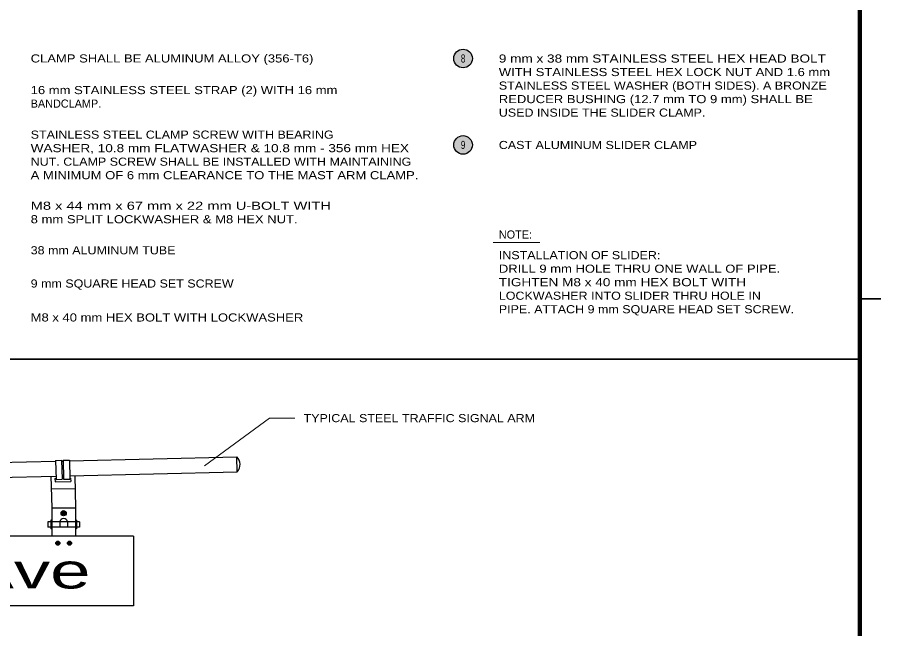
# Model space of a CAD drawing. Extents: x 312583 to 312853, y 144376 to 144586.
# Drawn here: x 312771.1 to 312850.9, y 144473.1 to 144529.7 of the extents above; entities that cross this region are included whole.
import ezdxf
from ezdxf.enums import TextEntityAlignment as Align

# ---------------------------------------------------------------- set-up
doc = ezdxf.new("R2010")
doc.units = 0
doc.header["$LTSCALE"] = 0.3
doc.layers.add('1', color=7, linetype='Continuous', lineweight=25)
doc.layers.add('2', color=7, linetype='Continuous', lineweight=13)

msp = doc.modelspace()

# ---------------------------------------------------------------- hatches: boundary and pattern name
at = {"layer": '1'}
for points in [[(312775.586, 144483.7997, 1), (312775.104, 144483.7997, 1)], [(312775.5147, 144483.7997, 1), (312775.1753, 144483.7997, 1)], [(312775.0002, 144481.0248, 1), (312774.6179, 144481.0248, 1)], [(312776.079, 144481.0248, 1), (312775.6967, 144481.0248, 1)]]:
    msp.add_hatch(color=256, dxfattribs=at).paths.add_polyline_path(points)
at = {"layer": '2'}
for points in [[(312813.1582, 144525.8569, 1), (312811.4379, 144525.8569, 1)], [(312813.1582, 144517.8617, 1), (312811.4379, 144517.8617, 1)]]:
    msp.add_hatch(color=256, dxfattribs=at).paths.add_polyline_path(points)

# ---------------------------------------------------------------- linework, layer by layer
at = {"layer": '1', "lineweight": 158}
msp.add_line((312849, 144423.1446), (312849, 144585.0846), dxfattribs=at)
at = {"layer": '1', "lineweight": 35}
msp.add_line((312849, 144503.6216), (312850.932, 144503.6216), dxfattribs=at)
at = {"layer": '1'}
for p, q in [((312775.3001, 144488.6997), (312775.8743, 144488.709)), ((312775.8743, 144488.6349), (312791.3668, 144489.0053)), ((312775.8743, 144488.709), (312775.9206, 144486.9495)), ((312791.4038, 144487.6348), (312791.3668, 144489.0053)), ((312749.9268, 144488.0237), (312774.5963, 144488.6071)), ((312774.5963, 144488.6812), (312775.1612, 144488.6997)), ((312774.5963, 144488.6812), (312774.6426, 144486.9217)), ((312775.1612, 144488.6997), (312775.2075, 144486.9402)), ((312775.1612, 144488.6164), (312775.3001, 144488.6256)), ((312775.3001, 144488.6997), (312775.3464, 144486.9402)), ((312749.9639, 144486.6532), (312774.6334, 144487.2366)), ((312774.1704, 144487.2273), (312774.2444, 144484.2825)), ((312775.1983, 144487.2458), (312775.3372, 144487.2551)), ((312775.9113, 144487.2644), (312791.4038, 144487.6348)), ((312776.3743, 144487.2736), (312776.4484, 144484.2825)), ((312774.5408, 144486.9958), (312774.6426, 144487.0051)), ((312774.5408, 144486.9958), (312774.55, 144486.6902)), ((312774.55, 144486.6902), (312776.0039, 144486.7273)), ((312774.6426, 144486.9217), (312775.2075, 144486.9402)), ((312775.2075, 144487.0051), (312775.3464, 144487.0143)), ((312775.3464, 144486.9402), (312775.9206, 144486.9495)), ((312775.9206, 144487.0329), (312775.9946, 144487.0329)), ((312775.9946, 144487.0329), (312776.0039, 144486.7273)), ((312774.1981, 144486.042), (312776.4021, 144486.0976)), ((312774.2444, 144484.2825), (312774.2444, 144481.6896)), ((312774.2444, 144484.2825), (312776.4484, 144484.2825)), ((312776.4484, 144484.2825), (312776.4484, 144481.6896)), ((312774.1704, 144483.1435), (312774.1704, 144482.3471)), ((312774.2444, 144483.1435), (312774.1704, 144483.1435)), ((312776.5225, 144483.1435), (312776.4484, 144483.1435)), ((312776.5225, 144483.1435), (312776.5225, 144482.3471)), ((312773.874, 144482.9861), (312773.874, 144482.4953)), ((312774.1704, 144482.9861), (312773.874, 144482.9861)), ((312774.1704, 144482.4953), (312773.874, 144482.4953)), ((312774.2444, 144482.3471), (312774.1704, 144482.3471)), ((312776.4484, 144482.9861), (312774.2444, 144482.9861)), ((312776.4484, 144482.4953), (312774.2444, 144482.4953)), ((312774.9945, 144482.9861), (312774.9945, 144482.4953)), ((312775.6983, 144482.9861), (312775.6983, 144482.4953)), ((312776.5225, 144482.3471), (312776.4484, 144482.3471)), ((312776.8188, 144482.9861), (312776.5225, 144482.9861)), ((312776.8188, 144482.4953), (312776.5225, 144482.4953)), ((312776.8188, 144482.9861), (312776.8188, 144482.4953)), ((312781.8194, 144481.6896), (312742.9075, 144481.6896)), ((312781.8194, 144481.6896), (312781.8194, 144475.2167)), ((312781.8194, 144475.2167), (312742.9075, 144475.2167))]:
    msp.add_line(p, q, dxfattribs=at)
at = {"layer": '1', "lineweight": 35}
msp.add_lwpolyline([(312727.3426, 144585.0846), (312727.3426, 144498.0376), (312849, 144498.0376)], dxfattribs=at)
at = {"layer": '1'}
for centre, radius in [((312775.345, 144483.7997), 0.241), ((312775.345, 144483.7997), 0.1697), ((312774.8091, 144481.0248), 0.1911), ((312775.8879, 144481.0248), 0.1911)]:
    msp.add_circle(centre, radius, dxfattribs=at)
for centre, radius, start, end in [((312790.7111, 144488.3018), 0.9617, 316.08276, 47.01356), ((312775.345, 144482.9614), 0.3533, 5.25702, 174.74298)]:
    msp.add_arc(centre, radius, start, end, dxfattribs=at)
at = {"layer": '2'}
for p, q in [((312815.067, 144508.8419), (312819.4101, 144508.8419)), ((312788.385, 144488.1904), (312794.3856, 144492.5798)), ((312794.3856, 144492.5798), (312796.7378, 144492.5798))]:
    msp.add_line(p, q, dxfattribs=at)
at = {"layer": '2', "lineweight": 25}
for centre in [(312812.2981, 144525.8569), (312812.2981, 144517.8617)]:
    msp.add_circle(centre, 0.8601, dxfattribs=at)

# ---------------------------------------------------------------- texts
at = {"layer": '1', "width": 1.55}
msp.add_text('Union Ave', height=3.236, dxfattribs=at).set_placement((312762.3588, 144476.8372), align=Align.CENTER)
at = {"layer": '2'}
for s, height, width, p in [('CLAMP SHALL BE ALUMINUM ALLOY (356-T6)', 0.7501, 1.2, (312772.2983, 144525.4862)), ('9 mm x 38 mm STAINLESS STEEL HEX HEAD BOLT', 0.7505, 1.25, (312815.6041, 144525.4785)), ('WITH STAINLESS STEEL HEX LOCK NUT AND 1.6 mm', 0.7505, 1.2, (312815.6041, 144524.228)), ('16 mm STAINLESS STEEL STRAP (2) WITH 16 mm', 0.7505, 1.2, (312772.2983, 144522.5599)), ('STAINLESS STEEL WASHER (BOTH SIDES). A BRONZE', 0.7505, 1.15, (312815.6041, 144522.9775)), ('REDUCER BUSHING (12.7 mm TO 9 mm) SHALL BE', 0.7505, 1.2, (312815.6041, 144521.727)), ('USED INSIDE THE SLIDER CLAMP.', 0.7505, 1.15, (312815.6041, 144520.4765)), ('STAINLESS STEEL CLAMP SCREW WITH BEARING', 0.7505, 1.15, (312772.2983, 144518.4394)), ('WASHER, 10.8 mm FLATWASHER & 10.8 mm - 356 mm HEX', 0.7505, 1.25, (312772.2983, 144517.1889)), ('CAST ALUMINUM SLIDER CLAMP', 0.7501, 1.15, (312815.6041, 144517.4818)), ('NUT. CLAMP SCREW SHALL BE INSTALLED WITH MAINTAINING', 0.7505, 1.15, (312772.2983, 144515.9384)), ('A MINIMUM OF 6 mm CLEARANCE TO THE MAST ARM CLAMP.', 0.7505, 1.2, (312772.2983, 144514.6879)), ('M8 x 44 mm x 67 mm x 22 mm U-BOLT WITH', 0.7505, 1.35, (312772.2983, 144511.8643)), ('8 mm SPLIT LOCKWASHER & M8 HEX NUT.', 0.7505, 1.2, (312772.2983, 144510.6138)), ('38 mm ALUMINUM TUBE', 0.7501, 1.15, (312772.2983, 144507.7434)), ('INSTALLATION OF SLIDER:', 0.7505, 1.15, (312815.6041, 144507.2913)), ('DRILL 9 mm HOLE THRU ONE WALL OF PIPE.', 0.7505, 1.2, (312815.6041, 144506.0408)), ('TIGHTEN M8 x 40 mm HEX BOLT WITH', 0.7505, 1.25, (312815.6041, 144504.7903)), ('9 mm SQUARE HEAD SET SCREW', 0.7501, 1.15, (312772.2983, 144504.669)), ('LOCKWASHER INTO SLIDER THRU HOLE IN', 0.7505, 1.15, (312815.6041, 144503.5398)), ('M8 x 40 mm HEX BOLT WITH LOCKWASHER', 0.7501, 1.2, (312772.2983, 144501.5298)), ('PIPE. ATTACH 9 mm SQUARE HEAD SET SCREW.', 0.7505, 1.15, (312815.6041, 144502.2893)), ('TYPICAL STEEL TRAFFIC SIGNAL ARM', 0.7501, 1.15, (312797.5434, 144492.2186))]:
    msp.add_text(s, height=height, dxfattribs=dict(at, width=width)).set_placement(p)
at = {"layer": '2', "width": 0.75}
for s, p in [('8', (312812.2981, 144525.4827)), ('9', (312812.2981, 144517.4911))]:
    msp.add_text(s, height=0.7501, dxfattribs=at).set_placement(p, align=Align.CENTER)
at = {"layer": '2'}
for s, p in [('BANDCLAMP.', (312772.2983, 144521.3094)), ('NOTE:', (312815.6041, 144509.2031))]:
    msp.add_text(s, height=0.7505, dxfattribs=at).set_placement(p)

doc.saveas('drawing.dxf')
